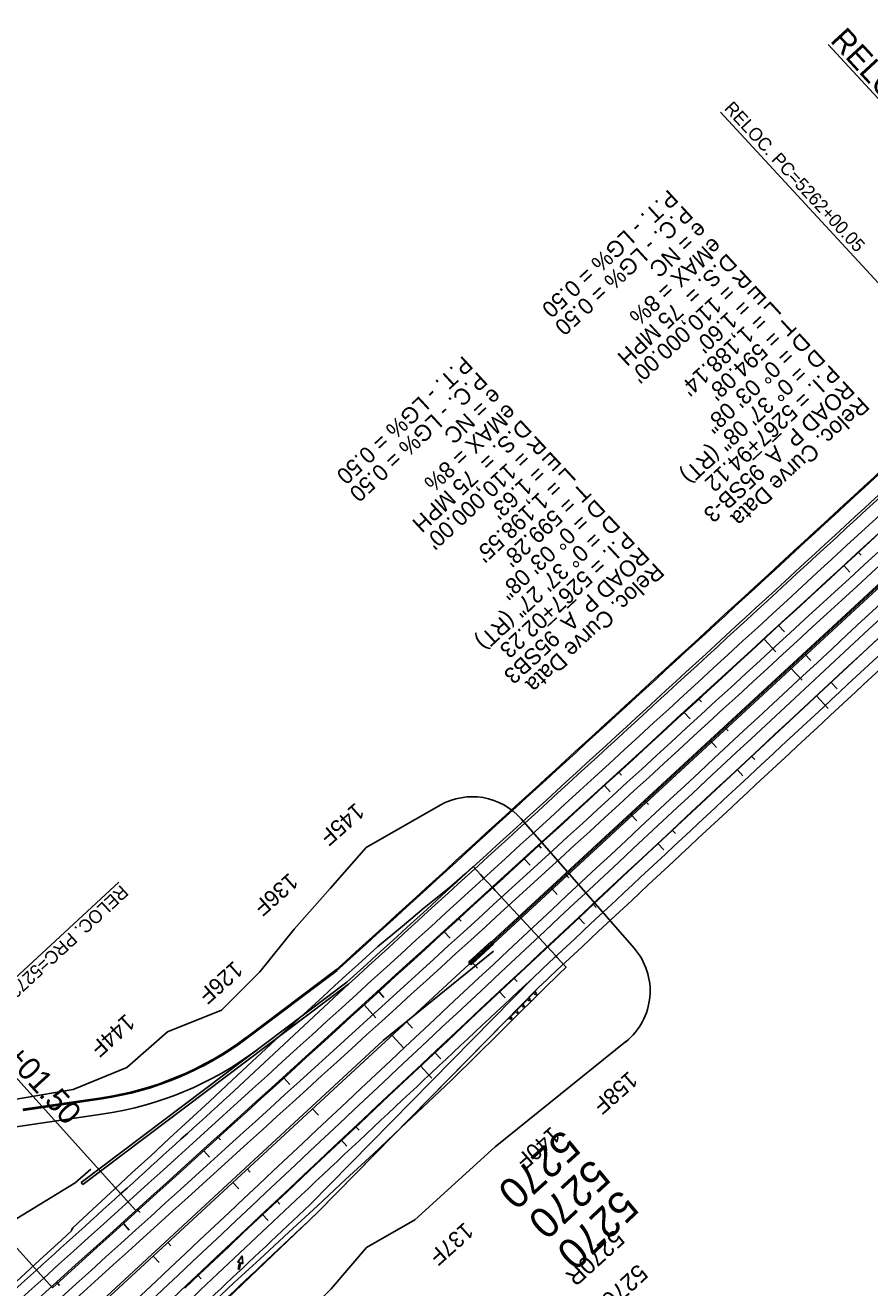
# Model space of a CAD drawing. Extents: x 2160876 to 2175990, y 601436 to 618246.
# Drawn here: x 2164670 to 2165449, y 606830 to 607994 of the extents above; entities that cross this region are included whole.
import ezdxf

# ---------------------------------------------------------------- set-up
doc = ezdxf.new("R2010")
doc.units = 0
for name, color, linetype in [('BNDY-ADJ', 7, 'Continuous'), ('BNDY-ADJ-TXT', 7, 'Continuous'), ('EX-UTIL-ELEC-TXT', 7, 'Continuous'), ('GN_Transparent 80', 7, 'Continuous'), ('RD_DTM_Major2', 7, 'Continuous'), ('RD_EX_BldgApp_Deck', 7, 'Continuous'), ('RD_EX_BldgApp_Sign', 7, 'Continuous'), ('RD_EX_BldgApp_Steps', 7, 'Continuous'), ('RD_EX_DV_Prop_Easement Lines', 7, 'Continuous'), ('RD_EX_DV_Prop_Property Lines', 7, 'Continuous'), ('RD_EX_DV_TX_Prop', 7, 'Continuous'), ('RD_EX_Fence_Gate', 7, 'Continuous'), ('RD_EX_RW', 7, 'Continuous'), ('RD_HC_Cl', 7, 'Continuous'), ('RD_HC_Data_Tic', 7, 'Continuous'), ('RD_HC_TX_Sta50', 7, 'Continuous'), ('RD_TX_RoadID', 7, 'Continuous')]:
    doc.layers.add(name, color=color, linetype=linetype)

msp = doc.modelspace()

# ---------------------------------------------------------------- linework, layer by layer
at = {"layer": 'BNDY-ADJ'}
msp.add_line((2172239.9, 613739.9), (2163704.8, 605858.6), dxfattribs=at)
at = {"layer": 'BNDY-ADJ-TXT'}
for centre, start, end in [((2090947.4, 688446.2), 312.100607, 312.719474), ((2240245.2, 526764.1), 132.719474, 133.338341)]:
    msp.add_arc(centre, 110000, start, end, dxfattribs=at)
at = {"layer": 'EX-UTIL-ELEC-TXT'}
for p, q in [((2164957.1, 607123), (2164874.6, 607060.8)), ((2164957.8, 607122.2), (2164875.2, 607060)), ((2164932.9, 606906.3), (2165138.6, 607115.5)), ((2164740.7, 607004.9), (2164667.9, 606994.2)), ((2164740.9, 607003.9), (2164668.1, 606993.2)), ((2164742.7, 606990), (2164670.1, 606979.3))]:
    msp.add_line(p, q, dxfattribs=at)
for centre, radius, start, end in [((2090947.4, 688446.2), 109958.7, 312.303996, 312.719474), ((2090947.4, 688446.2), 109959.7, 312.303996, 312.719474), ((2090947.4, 688446.2), 109988, 312.100607, 312.719474), ((2090947.4, 688446.2), 110000, 312.100607, 312.719474), ((2090947.4, 688446.2), 110012, 312.100607, 312.719474), ((2240245.2, 526764.1), 110012, 132.719474, 133.338341), ((2240245.2, 526764.1), 110000, 132.719474, 133.338341), ((2240245.2, 526764.1), 109988, 132.719474, 133.067682), ((2240245.2, 526764.1), 109988, 133.067682, 133.220424), ((2164698.2, 607294.8), 293, 278.2992, 306.927), ((2164698.2, 607294.8), 294, 278.2992, 307.0089), ((2164698.2, 607294.8), 308, 278.2992, 307.0089), ((2164712.5, 606690.4), 292, 98.3571, 124.6285), ((2240245.2, 526764.1), 109988, 133.220424, 133.338341), ((2240245.2, 526764.1), 109976, 133.220424, 133.338341), ((2238443, 525213.1), 110012, 132.100607, 132.719474)]:
    msp.add_arc(centre, radius, start, end, dxfattribs=at)
at = {"layer": 'GN_Transparent 80'}
for p, q in [((2168454, 610245.6), (2165100.2, 607148.7)), ((2168455.6, 610243.9), (2165101.8, 607146.9)), ((2165101.8, 607146.9), (2165100.2, 607148.7)), ((2164966.7, 607111.5), (2164721.8, 606926.8)), ((2164968.2, 607109.7), (2164723.2, 606925)), ((2164723.2, 606925), (2164721.8, 606926.8))]:
    msp.add_line(p, q, dxfattribs=at)
for radius, start in [(109973.7, 312.303996), (109976, 312.30394)]:
    msp.add_arc((2090947.4, 688446.2), radius, start, 312.719474, dxfattribs=at)
at = {"layer": 'RD_DTM_Major2'}
for p, q in [((2165375.9, 607401.6), (2165386.7, 607389.9)), ((2165302.4, 607333.8), (2165307.8, 607327.9)), ((2165228.9, 607266), (2165234.4, 607260.1)), ((2165155.5, 607198.1), (2165160.9, 607192.2)), ((2165082, 607130.3), (2165087.4, 607124.4)), ((2165008.5, 607062.4), (2165019.4, 607050.7)), ((2164935.1, 606994.6), (2164940.5, 606988.7)), ((2164861.6, 606926.7), (2164867, 606920.9)), ((2164788.1, 606858.9), (2164793.6, 606853))]:
    msp.add_line(p, q, dxfattribs=at)
at = {"layer": 'RD_EX_BldgApp_Deck'}
for p, q in [((2165099.9, 607149), (2165080, 607130.7)), ((2165099.9, 607149), (2165080, 607130.7)), ((2165097.3, 607145.9), (2165080.4, 607130.3)), ((2165098.8, 607144.2), (2165081.9, 607128.6)), ((2165102.1, 607146.6), (2165082.3, 607128.3)), ((2165082.3, 607128.3), (2165102.1, 607146.6)), ((2165089.2, 607138.5), (2165091.1, 607140.2)), ((2165091.1, 607140.2), (2165091.4, 607140.5)), ((2165092.7, 607138.5), (2165091.1, 607140.2)), ((2165091.4, 607140.5), (2165093.3, 607142.3)), ((2165093, 607138.8), (2165091.4, 607140.5)), ((2165093.3, 607142.3), (2165093.6, 607142.5)), ((2165094.9, 607140.6), (2165093.3, 607142.3)), ((2165093.6, 607142.5), (2165095.5, 607144.3)), ((2165095.2, 607140.8), (2165093.6, 607142.5)), ((2165095.5, 607144.3), (2165095.8, 607144.6)), ((2165097.1, 607142.6), (2165095.5, 607144.3)), ((2165095.8, 607144.6), (2165097.3, 607145.9)), ((2165097.4, 607142.9), (2165095.8, 607144.6)), ((2165100.2, 607148.7), (2165097.3, 607145.9)), ((2165097.3, 607145.9), (2165100.2, 607148.7)), ((2165098.8, 607144.2), (2165097.3, 607145.9)), ((2165101.8, 607146.9), (2165098.8, 607144.2)), ((2165101.8, 607146.9), (2165098.8, 607144.2)), ((2165099.9, 607149), (2165100.2, 607148.7)), ((2165100.2, 607148.7), (2165099.9, 607149)), ((2165102.1, 607146.6), (2165101.8, 607146.9)), ((2165102.1, 607146.6), (2165101.8, 607146.9)), ((2165082.3, 607128.3), (2165080, 607130.7)), ((2165080.3, 607130.4), (2165080, 607130.7)), ((2165082.3, 607128.3), (2165082, 607128.6)), ((2165083.9, 607130.4), (2165082.3, 607132.1)), ((2165082.6, 607132.4), (2165084.5, 607134.1)), ((2165084.1, 607130.7), (2165082.6, 607132.4)), ((2165084.5, 607134.1), (2165084.8, 607134.4)), ((2165086.1, 607132.4), (2165084.5, 607134.1)), ((2165084.8, 607134.4), (2165086.7, 607136.2)), ((2165086.4, 607132.7), (2165084.8, 607134.4)), ((2165086.7, 607136.2), (2165087, 607136.4)), ((2165088.3, 607134.5), (2165086.7, 607136.2)), ((2165087, 607136.4), (2165088.9, 607138.2)), ((2165088.6, 607134.7), (2165087, 607136.4)), ((2165088.9, 607138.2), (2165089.2, 607138.5)), ((2165090.5, 607136.5), (2165088.9, 607138.2)), ((2165090.8, 607136.8), (2165089.2, 607138.5))]:
    msp.add_line(p, q, dxfattribs=at)
for points in [[(2165098.8, 607144.2), (2165097.4, 607142.9), (2165097.1, 607142.6), (2165095.2, 607140.8), (2165094.9, 607140.6), (2165093, 607138.8), (2165092.7, 607138.5), (2165090.8, 607136.8), (2165090.5, 607136.5), (2165088.6, 607134.7), (2165088.3, 607134.5), (2165086.4, 607132.7), (2165086.1, 607132.4), (2165084.1, 607130.7), (2165083.9, 607130.4), (2165081.9, 607128.6)], [(2165080, 607130.7), (2165080.3, 607130.4), (2165080.4, 607130.3)], [(2165080.4, 607130.3), (2165082.3, 607132.1), (2165082.6, 607132.4)], [(2165081.9, 607128.6), (2165082, 607128.6), (2165082.3, 607128.3)]]:
    msp.add_lwpolyline(points, dxfattribs=at)
for radius in [1.67, 1.67, 1.27, 1.27]:
    msp.add_arc((2165081.2, 607129.5), radius, 132.7195, 312.7195, dxfattribs=at)
at = {"layer": 'RD_EX_BldgApp_Sign'}
for p, q in [((2165000.3, 607057.6), (2165102, 607140.1)), ((2165141.1, 607104.2), (2165115.3, 607077.6)), ((2165115.7, 607077.3), (2165141.4, 607103.8)), ((2165133.4, 607095.6), (2165134.6, 607096.8)), ((2165134.9, 607094.2), (2165133.4, 607095.6)), ((2165134.6, 607096.8), (2165136.1, 607095.4)), ((2165136.1, 607095.4), (2165134.9, 607094.2)), ((2165135.5, 607094.8), (2165136.4, 607093.9)), ((2165135.8, 607093.3), (2165137, 607094.6)), ((2165139, 607101.3), (2165140.2, 607102.6)), ((2165140.4, 607099.9), (2165139, 607101.3)), ((2165140.2, 607102.6), (2165141.6, 607101.2)), ((2165141.6, 607101.2), (2165140.4, 607099.9)), ((2165141, 607100.6), (2165141.9, 607099.7)), ((2165141.4, 607103.8), (2165141.1, 607104.2)), ((2165141.3, 607099.1), (2165142.5, 607100.3)), ((2165120.1, 607081.9), (2165119.7, 607082.2)), ((2165122.3, 607084.1), (2165123.5, 607085.3)), ((2165123.7, 607082.7), (2165122.3, 607084.1)), ((2165123.5, 607085.3), (2165124.9, 607084)), ((2165124.9, 607084), (2165123.7, 607082.7)), ((2165124.3, 607083.3), (2165125.2, 607082.5)), ((2165124.6, 607081.8), (2165125.8, 607083.1)), ((2165127.9, 607089.8), (2165129.1, 607091.1)), ((2165129.3, 607088.4), (2165127.9, 607089.8)), ((2165129.1, 607091.1), (2165130.5, 607089.7)), ((2165130.5, 607089.7), (2165129.3, 607088.4)), ((2165129.9, 607089.1), (2165130.8, 607088.2)), ((2165130.2, 607087.6), (2165131.4, 607088.8)), ((2165115.3, 607077.6), (2165115.7, 607077.3)), ((2165116.7, 607078.4), (2165117.9, 607079.6)), ((2165118.1, 607077), (2165116.7, 607078.4)), ((2165117.9, 607079.6), (2165119.4, 607078.2)), ((2165119.4, 607078.2), (2165118.1, 607077)), ((2165118.8, 607077.6), (2165119.7, 607076.7)), ((2165119, 607076.1), (2165120.3, 607077.3)), ((2165000.3, 607057.6), (2163734.9, 605889.1))]:
    msp.add_line(p, q, dxfattribs=at)
msp.add_lwpolyline([(2165115.3, 607077.6), (2164939.7, 606899), (2164849.6, 606813.1)], dxfattribs=at)
at = {"layer": 'RD_EX_BldgApp_Steps'}
for p, q in [((2172672.7, 614139.6), (2163700.6, 605854.7)), ((2165657.1, 607709.2), (2165410.9, 607975.9)), ((2165438.6, 607508), (2165441.3, 607505)), ((2165365, 607440.4), (2165370.4, 607434.5)), ((2165389.3, 607414), (2165394.7, 607408.1)), ((2165413.6, 607387.7), (2165419, 607381.9)), ((2165291.2, 607372.8), (2165293.9, 607369.9)), ((2165315.8, 607346.2), (2165318.5, 607343.2)), ((2165340.4, 607319.6), (2165343.1, 607316.7)), ((2165217.4, 607305.4), (2165220.1, 607302.4)), ((2165242.4, 607278.3), (2165245.1, 607275.4)), ((2165267.2, 607251.4), (2165269.9, 607248.5)), ((2165143.5, 607238), (2165146.2, 607235)), ((2164772.2, 606900.9), (2164479.3, 607225.1)), ((2165168.9, 607210.5), (2165171.6, 607207.6)), ((2165194.1, 607183.2), (2165196.9, 607180.3)), ((2165069.6, 607170.6), (2165072.3, 607167.7)), ((2165121.1, 607114.9), (2165123.8, 607111.9)), ((2164995.6, 607103.3), (2165001, 607097.4)), ((2165022, 607074.8), (2165027.4, 607068.9)), ((2165048.1, 607046.5), (2165053.6, 607040.6)), ((2164975.2, 606978), (2164978, 606975.1)), ((2164847.5, 606969), (2164850.1, 606966)), ((2164875, 606939.1), (2164877.7, 606936.2)), ((2164902.4, 606909.5), (2164905.1, 606906.6)), ((2164773.3, 606901.9), (2164776, 606899)), ((2164801.5, 606871.3), (2164804.3, 606868.4)), ((2164829.6, 606840.9), (2164832.4, 606838)), ((2164699.1, 606834.9), (2164701.8, 606831.9))]:
    msp.add_line(p, q, dxfattribs=at)
for centre, start, end in [((2091032.1, 688524.5), 312.095186, 312.719474), ((2240307.5, 526821.6), 132.719474, 133.335811), ((2238512.2, 525277.4), 132.095186, 132.719474)]:
    msp.add_arc(centre, 110000, start, end, dxfattribs=at)
at = {"layer": 'RD_EX_DV_Prop_Easement Lines'}
for points in [[(2164870.1, 606859), (2164866.1, 606853.3), (2164867.7, 606853.1)], [(2164867.7, 606853.1), (2164868, 606853.1), (2164866.4, 606847), (2164866.9, 606846.9)], [(2164866.9, 606846.9), (2164867.4, 606846.8), (2164869, 606852.8), (2164870.8, 606852), (2164870.1, 606859)]]:
    msp.add_lwpolyline(points, dxfattribs=at)
at = {"layer": 'RD_EX_DV_Prop_Property Lines'}
msp.add_lwpolyline([(2164730.7, 606938.9), (2164716.2, 606926.5), (2164476.9, 606780.3)], dxfattribs=at)
at = {"layer": 'RD_EX_Fence_Gate'}
for p, q in [((2164984.7, 607235.6), (2165052.8, 607274.5)), ((2165231.8, 607142.8), (2165127.7, 607261.9)), ((2164984.7, 607235.6), (2164951.5, 607197.9)), ((2164951.5, 607197.9), (2164918.1, 607160.4)), ((2164918.1, 607160.4), (2164886.4, 607121)), ((2165224.2, 607056.6), (2165103.5, 606959.6)), ((2165103.5, 606959.6), (2165029.4, 606892.4)), ((2165029.4, 606892.4), (2164985, 606866.8))]:
    msp.add_line(p, q, dxfattribs=at)
for points in [[(2164537.9, 606942.9), (2164531.9, 606955.8), (2164619.9, 606996.5), (2164714.3, 607012.5), (2164763.8, 607032.7), (2164801.3, 607065.7), (2164851.1, 607085.6), (2164886.4, 607121)], [(2164985, 606866.8), (2164952.2, 606828.7), (2164916.7, 606793.4)]]:
    msp.add_lwpolyline(points, dxfattribs=at)
for centre, start, end in [((2165082.5, 607222.4), 41.1644, 119.7089), ((2165186.6, 607103.3), 308.7929, 41.1644)]:
    msp.add_arc(centre, 60, start, end, dxfattribs=at)
at = {"layer": 'RD_EX_RW'}
for p, q in [((2165052.8, 607274.5), (2164984.7, 607235.6)), ((2165231.8, 607142.8), (2165127.7, 607261.9)), ((2164984.7, 607235.6), (2164951.5, 607197.9)), ((2164951.5, 607197.9), (2164918.1, 607160.4)), ((2165148.6, 607147.6), (2165104.3, 607195.3)), ((2165104.3, 607195.3), (2165148.6, 607147.6)), ((2164918.1, 607160.4), (2164886.4, 607121)), ((2165148.6, 607147.6), (2165151, 607145)), ((2165103.5, 606959.6), (2165224.2, 607056.6)), ((2165029.4, 606892.4), (2165103.5, 606959.6)), ((2164985, 606866.8), (2165029.4, 606892.4))]:
    msp.add_line(p, q, dxfattribs=at)
for points in [[(2165068.2, 607204.6), (2165075.8, 607211.3), (2165083.4, 607218), (2165090, 607210.7), (2165093.6, 607206.8), (2165095.9, 607204.4), (2165101.7, 607198.1), (2165103.5, 607196.1), (2165104.3, 607195.3)], [(2164654.1, 606828.2), (2164670.3, 606843.1), (2164683.3, 606855.1), (2164703.9, 606874), (2164712.9, 606882.2), (2164712.9, 606882.7), (2164713, 606883.4), (2164714.1, 606884.8), (2164732.2, 606901.8), (2164752.9, 606921.1), (2164768.4, 606935.6), (2164786.1, 606951.4), (2164803.3, 606967.5), (2164821.2, 606984.1), (2164840.2, 607001.5), (2164861.4, 607021.4), (2164870.3, 607029.7), (2164883.6, 607042.3), (2164904.8, 607061.6), (2164914.8, 607070.7), (2164927.2, 607081.9), (2164944.9, 607098.2), (2164955.5, 607107.9), (2164966.3, 607117.9), (2164977.1, 607127.7), (2164995.5, 607144.2), (2165007.3, 607154.1), (2165018.2, 607163.2), (2165025.7, 607169.6), (2165038.1, 607180), (2165059.7, 607197.2), (2165068.2, 607204.6)], [(2165151, 607145), (2165156.1, 607139.3), (2165159.3, 607135.9), (2165160.8, 607134.2), (2165167.3, 607127.2)], [(2164886.4, 607121), (2164851.1, 607085.6), (2164801.3, 607065.7), (2164763.8, 607032.7), (2164714.3, 607012.5), (2164619.9, 606996.5), (2164616.7, 606995)], [(2165167.3, 607127.2), (2165169, 607125.4), (2165162.4, 607118.9), (2165148.7, 607105.6), (2165139.1, 607095.8), (2165126.1, 607083.1), (2165105.8, 607062.9), (2165086.7, 607044), (2165063.3, 607021.2), (2165041.4, 607000.4), (2165016.6, 606977), (2164991.3, 606953.3), (2164965.6, 606929.4), (2164939.7, 606905.2), (2164913.3, 606880.8), (2164886.5, 606856.1), (2164862.8, 606834.5), (2164838.6, 606811.5)], [(2164916.7, 606793.4), (2164952.2, 606828.7), (2164985, 606866.8)]]:
    msp.add_lwpolyline(points, dxfattribs=at)
for centre, start, end in [((2165082.5, 607222.4), 41.1644, 119.7089), ((2165186.6, 607103.3), 308.7929, 41.1644)]:
    msp.add_arc(centre, 60, start, end, dxfattribs=at)
at = {"layer": 'RD_HC_Cl'}
for p, q in [((2165425.4, 607495.5), (2165430.8, 607489.6)), ((2165351.8, 607427.8), (2165362.6, 607416)), ((2165400.1, 607375.5), (2165410.9, 607363.8)), ((2165278.1, 607360.2), (2165283.5, 607354.3)), ((2165326.8, 607307.5), (2165332.2, 607301.6)), ((2165204.4, 607292.7), (2165209.8, 607286.8)), ((2165253.6, 607239.3), (2165259.1, 607233.5)), ((2165130.5, 607225.2), (2165135.9, 607219.3)), ((2165180.5, 607171.1), (2165185.9, 607165.3)), ((2165056.7, 607157.8), (2165062.1, 607151.9)), ((2165107.4, 607102.8), (2165112.9, 607097)), ((2164982.7, 607090.4), (2164993.5, 607078.6)), ((2165034.4, 607034.5), (2165045.3, 607022.8)), ((2164908.8, 607023.2), (2164914.1, 607017.2)), ((2164961.5, 606966.1), (2164966.9, 606960.3)), ((2164834.7, 606956), (2164840.1, 606950)), ((2164888.6, 606897.6), (2164894.1, 606891.8)), ((2164760.6, 606888.8), (2164766, 606882.9))]:
    msp.add_line(p, q, dxfattribs=at)
at = {"layer": 'RD_HC_TX_Sta50'}
for p, q in [((2165572.4, 607631), (2165311.5, 607913.6)), ((2164538.9, 607002.7), (2164756.5, 607203.6)), ((2164695.2, 606829.7), (2164538.9, 607002.7))]:
    msp.add_line(p, q, dxfattribs=at)
at = {"layer": 'RD_TX_RoadID'}
for p, q in [((2164968.2, 607109.7), (2164858.6, 607007.3)), ((2164939.7, 606899), (2165145.5, 607108.4))]:
    msp.add_line(p, q, dxfattribs=at)
for centre, radius, start, end in [((2090947.4, 688446.2), 109976, 312.30394, 312.719474), ((2090947.4, 688446.2), 110022, 312.100607, 312.719474), ((2240245.2, 526764.1), 110022, 132.719474, 133.338341), ((2240245.2, 526764.1), 109978, 132.719474, 133.067545), ((2090947.4, 688446.2), 109978, 312.100607, 312.2258), ((2240245.2, 526764.1), 109966, 133.220424, 133.338341), ((2238443, 525213.1), 110022, 132.100607, 132.719474)]:
    msp.add_arc(centre, radius, start, end, dxfattribs=at)

# ---------------------------------------------------------------- texts
at = {"layer": 'RD_EX_BldgApp_Steps'}
for s, height, rotation, p in [('RELOC. PC=5261+02.95', 21, 312.7195, (2165411.9, 607979.1)), ('P.T. - LG% = 0.50', 15, 222.8068, (2165074.2, 607689.7)), ('P.C. - LG% = 0.50', 15, 222.8068, (2165087.7, 607675)), ('e = NC', 15, 222.8068, (2165101.3, 607660.3)), ('eMAX = 8%', 15, 222.8068, (2165114.9, 607645.7)), ('D.S. =  75 MPH', 15, 222.8068, (2165128.5, 607631)), ("R = 110,000.00'", 15, 222.8068, (2165142.1, 607616.3)), ("E = 1.63'", 15, 222.8068, (2165155.7, 607601.6)), ("L = 1,198.55'", 15, 222.8068, (2165169.3, 607587)), ("T = 599.28'", 15, 222.8068, (2165182.9, 607572.3)), ('D = 0° 03\' 08"', 15, 222.8068, (2165196.5, 607557.6)), ('D', 15, 222.8068, (2165210.1, 607543)), ('    = 0° 37\' 27" (RT)', 15, 222.8068, (2165210.1, 607543)), ('P.I. = 5267+02.23', 15, 222.8068, (2165223.6, 607528.3)), ('ROAD P_A_95SB3', 15, 222.8068, (2165237.2, 607513.6)), ('Reloc. Curve Data', 15, 222.8068, (2165250.8, 607498.9)), ('RELOC. PRC=5273+01.50', 21, 312.0952, (2164481.9, 607228.5)), ('5270', 28, 222.2522, (2165165.6, 606976.8)), ('5270', 28, 222.7195, (2165193.1, 606949.7)), ('5270', 28, 223.1708, (2165219, 606921.6))]:
    msp.add_text(s, height=height, rotation=rotation, dxfattribs=at).set_placement(p)
at = {"layer": 'RD_EX_DV_TX_Prop'}
msp.add_text('5270', height=16, rotation=222.7195, dxfattribs=at).set_placement((2165235.2, 606852.5))
at = {"layer": 'RD_EX_Fence_Gate'}
for s, rotation, p in [('145F', 221.3554, (2164974.8, 607277.7)), ('136F', 221.5463, (2164913.6, 607213)), ('126F', 221.7373, (2164862.6, 607131.9)), ('144F', 221.9283, (2164762.9, 607083.1)), ('158F', 221.3554, (2165226.9, 607030.1)), ('140F', 221.5463, (2165155.4, 606979.1)), ('137F', 221.7373, (2165075.4, 606890.9))]:
    msp.add_text(s, height=15, rotation=rotation, dxfattribs=at).set_placement(p)
at = {"layer": 'RD_HC_Data_Tic'}
msp.add_text('5270R', height=16, rotation=222.3028, dxfattribs=at).set_placement((2165213.8, 606884.3))
at = {"layer": 'RD_HC_TX_Sta50'}
for s, height, rotation, p in [('RELOC. PC=5262+00.05', 12, 312.7195, (2165314.2, 607916.6)), ('P.T. - LG% = 0.50', 15, 222.7195, (2165263.7, 607843.1)), ('P.C. - LG% = 0.50', 15, 222.7195, (2165277.3, 607828.4)), ('e = NC', 15, 222.7195, (2165290.8, 607813.7)), ('eMAX = 8%', 15, 222.7195, (2165304.4, 607799)), ('D.S. =  75 MPH', 15, 222.7195, (2165318, 607784.3)), ("R = 110,000.00'", 15, 222.7195, (2165331.5, 607769.6)), ("E = 1.60'", 15, 222.7195, (2165345.1, 607754.9)), ("L = 1,188.14'", 15, 222.7195, (2165358.7, 607740.3)), ("T = 594.08'", 15, 222.7195, (2165372.2, 607725.6)), ('D = 0° 03\' 08"', 15, 222.7195, (2165385.8, 607710.9)), ('D', 15, 222.7195, (2165399.4, 607696.2)), ('    = 0° 37\' 08" (RT)', 15, 222.7195, (2165399.4, 607696.2)), ('P.I. = 5267+94.12', 15, 222.7195, (2165412.9, 607681.5)), ('ROAD P_A_95SB-3', 15, 222.7195, (2165426.5, 607666.8)), ('Reloc. Curve Data', 15, 222.7195, (2165440.1, 607652.1)), ('RELOC. PRC=5273+88.19', 12, 222.7195, (2164758.3, 607201.7))]:
    msp.add_text(s, height=height, rotation=rotation, dxfattribs=at).set_placement(p)

doc.saveas('drawing.dxf')
